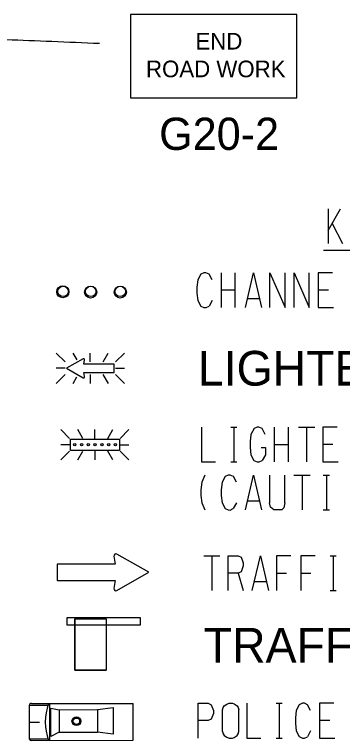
# Model space of a CAD drawing. Extents: x -1809 to 1557, y -1087 to 44.
# Drawn here: x -1310.2 to -1215.7, y -166.1 to 43.1 of the extents above; entities that cross this region are included whole.
import ezdxf

# ---------------------------------------------------------------- set-up
doc = ezdxf.new("R2010")
doc.units = 0
for name, color, linetype in [('Level 1', 7, 'Continuous'), ('MT_SCRATCH_LEVEL_E', 7, 'Continuous'), ('MT_STAGE_1A_NOTES', 7, 'Continuous'), ('PAVT_EDGE_PR', 7, 'Continuous'), ('TRAFFIC_SIGNS_PR', 7, 'Continuous'), ('TYPICAL_TEXT_DIMEN_EX', 7, 'Continuous')]:
    doc.layers.add(name, color=color, linetype=linetype)

msp = doc.modelspace()

# ---------------------------------------------------------------- linework, layer by layer
at = {"layer": 'Level 1'}
for p, q in [((-1305.91, -156.08), (-1305.91, -155.94)), ((-1305.91, -155.96), (-1305.91, -155.95)), ((-1305.89, -165.66), (-1305.91, -156.08)), ((-1305.37, -155.45), (-1276.07, -155.38)), ((-1299.73, -164.93), (-1299.75, -156.75)), ((-1299.75, -156.75), (-1297.4, -157.22)), ((-1286.34, -157.19), (-1281.81, -156.61)), ((-1281.81, -156.61), (-1281.8, -164.23)), ((-1276.05, -166.01), (-1276.07, -155.38)), ((-1297.4, -157.22), (-1286.34, -157.19)), ((-1297.4, -157.22), (-1297.38, -163.7)), ((-1286.34, -157.19), (-1286.33, -163.68)), ((-1297.38, -163.7), (-1299.73, -164.93)), ((-1297.38, -163.7), (-1286.33, -163.68)), ((-1281.8, -164.23), (-1286.33, -163.68)), ((-1305.89, -165.72), (-1305.89, -165.58)), ((-1305.43, -166.08), (-1276.05, -166.01))]:
    msp.add_line(p, q, dxfattribs=at)
at = {"layer": 'MT_SCRATCH_LEVEL_E'}
for p, q in [((-1271.54, -117.6), (-1280.71, -112.39)), ((-1281.57, -113), (-1281.18, -115.25)), ((-1281.18, -115.25), (-1297.97, -115.25)), ((-1297.97, -115.25), (-1297.97, -119.99)), ((-1280.71, -122.85), (-1271.54, -117.6)), ((-1297.97, -119.99), (-1281.18, -119.99)), ((-1281.18, -119.99), (-1281.57, -122.25))]:
    msp.add_line(p, q, dxfattribs=at)
for centre, start, end in [((-1280.99, -112.91), 60.4248, 189.9638), ((-1280.99, -122.33), 170.0362, 299.7731)]:
    msp.add_arc(centre, 0.586, start, end, dxfattribs=at)
at = {"layer": 'MT_STAGE_1A_NOTES'}
for p, q in [((-1292.85, -131.04), (-1292.85, -145.78)), ((-1283.79, -131.04), (-1283.79, -145.78)), ((-1292.85, -145.78), (-1283.79, -145.78))]:
    msp.add_line(p, q, dxfattribs=at)
for points in [[(-1273.95, -130.72), (-1295.1, -130.72), (-1295.1, -132.71), (-1273.95, -132.71)], [(-1292.85, -131.04), (-1283.79, -131.04), (-1283.79, -145.78), (-1292.85, -145.78)]]:
    msp.add_lwpolyline(points, close=True, dxfattribs=at)
msp.add_open_spline([(-1370.17, 20.96), (-1323.04, 20.96), (-1407.58, 40.22), (-1285.69, 34.85)], degree=2, dxfattribs=at)
at = {"layer": 'PAVT_EDGE_PR'}
for p, q in [((-1305.91, -155.94), (-1300.61, -155.93)), ((-1300.02, -166.07), (-1300.05, -155.46)), ((-1305.9, -160.77), (-1303.03, -160.78)), ((-1305.89, -165.65), (-1300.56, -165.64))]:
    msp.add_line(p, q, dxfattribs=at)
for centre, radius in [((-1296.28, -36.75), 1.74), ((-1296.22, -36.66), 1.51), ((-1288.28, -36.84), 1.74), ((-1288.26, -36.66), 1.51), ((-1279.73, -36.84), 1.74), ((-1279.76, -36.66), 1.51), ((-1292.39, -160.53), 1.27), ((-1292.39, -160.51), 1.2), ((-1292.39, -160.54), 0.93)]:
    msp.add_circle(centre, radius, dxfattribs=at)
for centre, radius, start, end in [((-1305.45, -155.91), 0.469, 80.7294, 183.4934), ((-1285.79, -160.69), 15.57, 160.2947, 200.2014), ((-1305.44, -165.61), 0.469, 194.1849, 275.0781)]:
    msp.add_arc(centre, radius, start, end, dxfattribs=at)
at = {"layer": 'TRAFFIC_SIGNS_PR'}
for p, q in [((-1298.19, -54.44), (-1295.66, -56.97)), ((-1292.14, -56.4), (-1293.28, -54.43)), ((-1288.38, -56.97), (-1288.38, -54.43)), ((-1284.66, -56.97), (-1283.19, -54.43)), ((-1281.1, -56.97), (-1278.56, -54.43)), ((-1295.66, -58.8), (-1298.19, -58.8)), ((-1298.19, -63.16), (-1295.66, -60.63)), ((-1288.38, -60.63), (-1288.38, -63.17)), ((-1283.17, -63.17), (-1284.64, -60.63)), ((-1281.1, -58.8), (-1278.56, -58.8)), ((-1281.1, -60.63), (-1278.56, -63.17)), ((-1293.3, -63.17), (-1292.22, -61.28)), ((-1296.88, -76.48), (-1294.34, -79.02)), ((-1290.5, -79.02), (-1291.96, -76.48)), ((-1287.07, -79.02), (-1287.07, -76.48)), ((-1283.34, -79.02), (-1281.88, -76.48)), ((-1279.79, -79.02), (-1277.25, -76.48)), ((-1294.34, -80.85), (-1296.88, -80.85)), ((-1292.87, -80.85), (-1292.87, -80.85)), ((-1290.91, -80.85), (-1290.91, -80.85)), ((-1288.96, -80.85), (-1288.96, -80.85)), ((-1287, -80.85), (-1287, -80.85)), ((-1285.04, -80.85), (-1285.04, -80.85)), ((-1283.09, -80.85), (-1283.09, -80.85)), ((-1281.13, -80.85), (-1281.13, -80.85)), ((-1279.79, -80.85), (-1277.25, -80.85)), ((-1296.88, -85.22), (-1294.34, -82.68)), ((-1291.99, -85.22), (-1290.52, -82.68)), ((-1287.07, -82.68), (-1287.07, -85.22)), ((-1281.86, -85.22), (-1283.32, -82.68)), ((-1279.79, -82.68), (-1277.25, -85.22))]:
    msp.add_line(p, q, dxfattribs=at)
for points in [[(-1276.84, 19.15), (-1228.84, 19.15), (-1228.84, 43.15), (-1276.84, 43.15)], [(-1280, -82.47), (-1294.13, -82.47), (-1294.13, -79.23), (-1280, -79.23)]]:
    msp.add_lwpolyline(points, close=True, dxfattribs=at)
for points in [[(-1290.47, -56.09), (-1295.25, -58.8), (-1290.47, -61.54)], [(-1290.02, -61.21), (-1290.23, -60.05), (-1281.48, -60.05), (-1281.48, -57.58), (-1290.23, -57.58), (-1290.02, -56.41)]]:
    msp.add_lwpolyline(points, dxfattribs=at)
for centre in [(-1292.85, -80.85), (-1290.91, -80.85), (-1288.96, -80.85), (-1287, -80.85), (-1285.04, -80.85), (-1283.09, -80.85), (-1281.13, -80.85)]:
    msp.add_circle(centre, 0.341, dxfattribs=at)
for centre, start, end in [((-1290.33, -56.36), 350.7308, 118.8916), ((-1290.33, -61.27), 241.4833, 9.9593)]:
    msp.add_arc(centre, 0.307, start, end, dxfattribs=at)
at = {"layer": 'TYPICAL_TEXT_DIMEN_EX'}
for p, q in [((-1221.19, -24.73), (-1201.01, -24.73)), ((-1257.32, -165.37), (-1257.32, -155.37)), ((-1257.32, -155.37), (-1254.4, -155.37)), ((-1254.4, -155.37), (-1253.53, -155.79)), ((-1253.53, -155.79), (-1252.91, -157.4)), ((-1250.29, -157.25), (-1250.14, -156.58)), ((-1250.14, -156.58), (-1249.78, -156.07)), ((-1249.78, -156.07), (-1249.06, -155.59)), ((-1249.06, -155.59), (-1248.37, -155.37)), ((-1248.37, -155.37), (-1247.43, -155.37)), ((-1247.43, -155.37), (-1246.97, -155.55)), ((-1246.97, -155.55), (-1246.09, -156.12)), ((-1246.09, -156.12), (-1245.78, -156.58)), ((-1245.78, -156.58), (-1245.62, -157.25)), ((-1243.32, -155.37), (-1243.32, -165.37)), ((-1234.86, -155.37), (-1233.11, -155.37)), ((-1233.99, -155.37), (-1233.99, -165.37)), ((-1228.15, -155.76), (-1229.05, -157.4)), ((-1227.28, -155.37), (-1228.15, -155.76)), ((-1226.7, -155.37), (-1227.28, -155.37)), ((-1225.78, -155.76), (-1226.7, -155.37)), ((-1224.91, -157.4), (-1225.78, -155.76)), ((-1218.24, -155.37), (-1222.32, -155.37)), ((-1222.32, -155.37), (-1222.32, -165.37)), ((-1252.91, -158.29), (-1253.53, -159.96)), ((-1252.91, -157.4), (-1252.91, -158.29)), ((-1250.29, -163.5), (-1250.29, -157.25)), ((-1245.62, -163.5), (-1245.62, -157.25)), ((-1229.05, -157.4), (-1229.3, -159.54)), ((-1254.4, -160.32), (-1257.32, -160.32)), ((-1253.53, -159.96), (-1254.4, -160.32)), ((-1229.3, -159.54), (-1229.3, -161.21)), ((-1219.4, -160.37), (-1222.32, -160.37)), ((-1229.3, -161.21), (-1229.05, -163.34)), ((-1250.29, -163.5), (-1250.14, -164.17)), ((-1250.14, -164.17), (-1249.78, -164.67)), ((-1249.78, -164.67), (-1249.06, -165.15)), ((-1249.06, -165.15), (-1248.37, -165.37)), ((-1247.43, -165.37), (-1246.97, -165.2)), ((-1246.97, -165.2), (-1246.09, -164.62)), ((-1246.09, -164.62), (-1245.78, -164.17)), ((-1245.78, -164.17), (-1245.62, -163.5)), ((-1229.05, -163.34), (-1228.15, -164.96)), ((-1228.15, -164.96), (-1227.28, -165.38)), ((-1226.68, -165.4), (-1225.8, -165.01)), ((-1224.91, -163.34), (-1225.8, -165.01)), ((-1248.37, -165.37), (-1247.43, -165.37)), ((-1243.32, -165.37), (-1239.24, -165.37)), ((-1234.86, -165.37), (-1233.11, -165.37)), ((-1227.28, -165.38), (-1226.68, -165.4)), ((-1222.32, -165.37), (-1217.95, -165.37))]:
    msp.add_line(p, q, dxfattribs=at)
for points in [[(-1219.83, -12.89), (-1219.83, -22.89)], [(-1219.83, -19.14), (-1216.33, -12.89)], [(-1218.66, -17.05), (-1215.75, -22.89)], [(-1254.15, -31.69), (-1255.06, -31.3), (-1255.64, -31.3), (-1256.52, -31.69), (-1257.41, -33.33)], [(-1250.68, -31.3), (-1250.68, -41.3)], [(-1246.6, -41.3), (-1246.6, -31.3)], [(-1243.68, -41.3), (-1241.35, -31.3)], [(-1241.35, -31.3), (-1239.02, -41.3)], [(-1236.68, -41.3), (-1236.68, -31.3)], [(-1236.68, -31.3), (-1232.27, -41.3)], [(-1232.27, -41.3), (-1232.27, -31.3)], [(-1229.68, -41.3), (-1229.68, -31.3)], [(-1229.68, -31.3), (-1225.27, -41.3)], [(-1225.27, -41.3), (-1225.27, -31.3)], [(-1218.6, -31.3), (-1222.68, -31.3)], [(-1222.68, -31.3), (-1222.68, -41.3)], [(-1257.41, -33.33), (-1257.67, -35.46), (-1257.67, -37.13), (-1257.41, -39.27)], [(-1253.27, -33.33), (-1254.15, -31.69)], [(-1250.68, -36.24), (-1246.6, -36.24)], [(-1219.77, -36.3), (-1222.68, -36.3)], [(-1257.41, -39.27), (-1256.52, -40.88), (-1255.64, -41.3), (-1255.04, -41.32), (-1254.17, -40.93)], [(-1253.27, -39.27), (-1254.17, -40.93)], [(-1239.6, -38.8), (-1243.1, -38.8)], [(-1222.68, -41.3), (-1218.31, -41.3)], [(-1256.37, -75.82), (-1256.37, -85.82)], [(-1247.91, -75.82), (-1246.16, -75.82)], [(-1247.04, -75.82), (-1247.04, -85.82)], [(-1238.83, -76.19), (-1239.8, -75.82), (-1240.34, -75.82), (-1241.2, -76.21), (-1242.1, -77.85)], [(-1237.96, -77.85), (-1238.83, -76.19)], [(-1235.37, -75.82), (-1235.37, -85.82)], [(-1231.29, -85.82), (-1231.29, -75.82)], [(-1228.37, -75.82), (-1223.7, -75.82)], [(-1226.04, -75.82), (-1226.04, -85.82)], [(-1217.29, -75.82), (-1221.37, -75.82)], [(-1221.37, -75.82), (-1221.37, -85.82)], [(-1242.1, -77.85), (-1242.35, -79.96), (-1242.36, -81.63), (-1242.1, -83.79)], [(-1235.37, -80.77), (-1231.29, -80.77)], [(-1218.45, -80.82), (-1221.37, -80.82)], [(-1239.16, -81.65), (-1237.94, -81.65)], [(-1237.94, -81.65), (-1237.94, -83.76)], [(-1242.1, -83.79), (-1241.22, -85.38), (-1240.33, -85.82), (-1239.73, -85.81), (-1238.83, -85.43)], [(-1237.94, -83.76), (-1238.83, -85.43)], [(-1256.37, -85.82), (-1252.29, -85.82)], [(-1247.91, -85.82), (-1246.16, -85.82)], [(-1221.37, -85.82), (-1217, -85.82)], [(-1255.36, -89.63), (-1256.26, -91.67), (-1256.53, -93.8), (-1256.53, -95.47), (-1256.26, -97.6), (-1255.36, -99.63)], [(-1247.16, -90.03), (-1248.07, -89.63), (-1248.66, -89.63), (-1249.53, -90.03), (-1250.42, -91.67)], [(-1243.7, -99.63), (-1241.36, -89.63)], [(-1241.36, -89.63), (-1239.03, -99.63)], [(-1236.7, -89.63), (-1236.7, -97.55)], [(-1232.32, -97.55), (-1232.32, -89.63)], [(-1229.7, -89.63), (-1225.03, -89.63)], [(-1227.36, -89.63), (-1227.36, -99.63)], [(-1221.24, -89.63), (-1219.49, -89.63)], [(-1220.36, -89.63), (-1220.36, -99.63)], [(-1250.42, -91.67), (-1250.68, -93.8), (-1250.68, -95.47), (-1250.42, -97.6)], [(-1246.28, -91.67), (-1247.16, -90.03)], [(-1250.42, -97.6), (-1249.53, -99.22), (-1248.65, -99.64), (-1248.05, -99.66), (-1247.18, -99.27)], [(-1246.28, -97.6), (-1247.18, -99.27)], [(-1239.61, -97.13), (-1243.11, -97.13)], [(-1232.32, -97.55), (-1232.61, -99.01), (-1233.2, -99.63), (-1235.53, -99.63), (-1236.42, -98.85), (-1236.7, -97.55)], [(-1221.24, -99.63), (-1219.49, -99.63)], [(-1255.7, -112.87), (-1251.04, -112.87)], [(-1253.37, -112.87), (-1253.37, -122.87)], [(-1248.7, -122.87), (-1248.7, -112.87)], [(-1248.7, -112.87), (-1245.79, -112.87)], [(-1245.78, -112.87), (-1244.91, -113.29), (-1244.29, -114.9), (-1244.29, -115.79), (-1244.91, -117.45), (-1245.79, -117.82)], [(-1241.7, -122.87), (-1239.37, -112.87)], [(-1239.37, -112.87), (-1237.04, -122.87)], [(-1230.62, -112.87), (-1234.7, -112.87)], [(-1234.7, -112.87), (-1234.7, -122.87)], [(-1223.62, -112.87), (-1227.7, -112.87)], [(-1227.7, -112.87), (-1227.7, -122.87)], [(-1219.24, -112.87), (-1217.49, -112.87)], [(-1218.37, -112.87), (-1218.37, -122.87)], [(-1245.79, -117.82), (-1248.7, -117.82)], [(-1245.79, -117.82), (-1244.29, -122.87)], [(-1234.7, -117.82), (-1231.8, -117.82)], [(-1227.7, -117.82), (-1224.8, -117.82)], [(-1237.62, -120.37), (-1241.12, -120.37)], [(-1219.24, -122.87), (-1217.49, -122.87)]]:
    msp.add_lwpolyline(points, dxfattribs=at)

# ---------------------------------------------------------------- texts
at = {"layer": 'TRAFFIC_SIGNS_PR'}
for s, height, p in [('END', 4.789, (-1258.09, 33.06)), ('ROAD WORK', 4.789, (-1272.33, 25.07)), ('G20-2', 9.3, (-1268.55, 4.12))]:
    msp.add_text(s, height=height, dxfattribs=at).set_placement(p)
at = {"layer": 'TYPICAL_TEXT_DIMEN_EX'}
for s, p in [('LIGHTED ARROW PANEL', (-1257.39, -63.81)), ('TRAFFIC REGULATOR', (-1255.7, -143.62))]:
    msp.add_text(s, height=10, dxfattribs=at).set_placement(p)

doc.saveas('drawing.dxf')
